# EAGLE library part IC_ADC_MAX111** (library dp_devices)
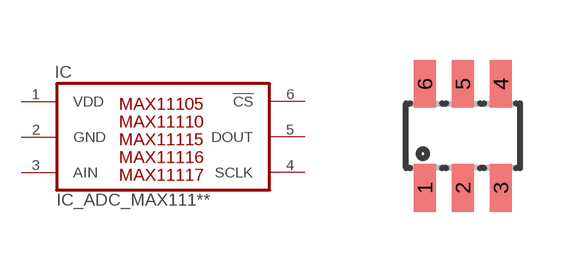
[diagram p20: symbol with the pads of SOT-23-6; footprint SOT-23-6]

Designator prefix IC

## IC_ADC_MAX111-SOT-23-6  [SOT-23-6]
1  VDD  pwr
2  GND  pwr
3  AIN  in
4  SCLK  in
5  DOUT  out
6  !CS  in

## Footprint SOT-23-6 (pad centres in mm)
smd 0.55 x 1.2: 1 -0.95,-1.3; 2 0,-1.3; 3 0.95,-1.3; 4 0.95,1.3; 5 0,1.3; 6 -0.95,1.3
